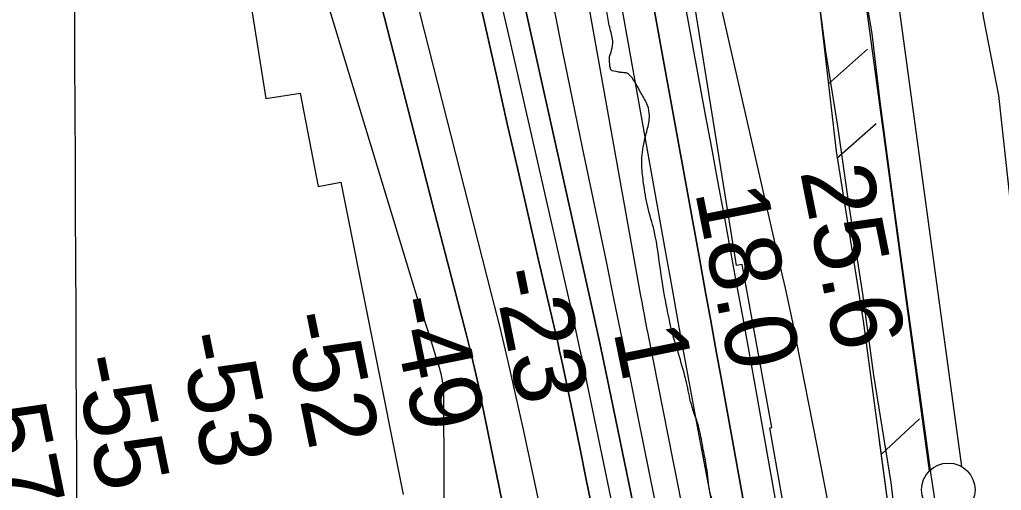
# Model space of a CAD drawing. Extents: x 3419139 to 3457078, y 540382 to 565875.
# Drawn here: x 3439010 to 3439927, y 553958 to 554398 of the extents above; entities that cross this region are included whole.
import ezdxf

# ---------------------------------------------------------------- set-up
doc = ezdxf.new("R2010")
doc.units = 0
for name, color, linetype in [('V-FLOD-BASE', 7, 'Continuous'), ('V-GRID-MAJR', 7, 'Continuous'), ('V-LEVE-TOET', 7, 'Continuous'), ('V-RIVR-EDGE', 7, 'Continuous'), ('V-RIVR-RANG', 7, 'Continuous'), ('V-RRAP-FSHR', 7, 'Continuous'), ('V-RRAP-RVMT', 7, 'Continuous'), ('V-SURV-LINE', 7, 'Continuous'), ('V-TOPO-DPTH', 7, 'Continuous'), ('V-TOPO-MAJR', 7, 'Continuous'), ('V-TOPO-MINR', 7, 'Continuous'), ('V-TOPO-WATR', 7, 'Continuous')]:
    doc.layers.add(name, color=color, linetype=linetype)

msp = doc.modelspace()

# ---------------------------------------------------------------- linework, layer by layer
at = {"layer": 'V-FLOD-BASE'}
msp.add_lwpolyline([(3439732.26, 554810.44), (3439729.04, 554757.67), (3439727.3, 554731.01), (3439727.56, 554720.62), (3439730.89, 554708.26), (3439738.97, 554680.73), (3439756.22, 554612.19), (3439779.58, 554519.49), (3439793.75, 554456.58), (3439805.94, 554385.24), (3439813.65, 554321.78), (3439825.79, 554230.52), (3439838.21, 554139.53), (3439850.64, 554050.23), (3439861.12, 553972.72), (3439871.35, 553905.32)], dxfattribs=at)
at = {"layer": 'V-GRID-MAJR'}
msp.add_spline([(3439098.77, 545841.13), (3439072.33, 551898.65), (3439045.89, 557959.64), (3439019.44, 564020.65), (3439019.42, 564024.1)], degree=3, dxfattribs=at)
at = {"layer": 'V-LEVE-TOET'}
for points in [[(3439831.14, 553904.45), (3439824, 553965.54), (3439807.98, 554065.87), (3439797.52, 554142.09), (3439784.54, 554226.44), (3439774.35, 554298.74), (3439763.02, 554368.52), (3439755.6, 554425.97), (3439747.08, 554499.67), (3439740.46, 554540.86), (3439732.42, 554577.58), (3439715.19, 554638.69), (3439705.74, 554670.93), (3439701.02, 554686.07), (3439697.68, 554697.28), (3439694.62, 554706.53), (3439693.79, 554711.01), (3439692.7, 554724.18), (3439694.18, 554758.08), (3439695.68, 554799.26), (3439691, 554838.2), (3439682.74, 554897.61), (3439664.2, 554994.02)], [(3439838.15, 554946.85), (3439848.36, 554881), (3439850.86, 554871.19), (3439853.91, 554856.89), (3439856.66, 554834.2), (3439855.48, 554808.7), (3439857.66, 554784.05), (3439867.27, 554698.3), (3439882.48, 554615.07), (3439891.04, 554559.86), (3439900.38, 554480.84), (3439910, 554400.98), (3439924.39, 554327.55), (3439935.64, 554224.99)]]:
    msp.add_lwpolyline(points, dxfattribs=at)
at = {"layer": 'V-RIVR-EDGE'}
msp.add_spline([(3439897.96, 552838.81), (3439895.18, 552852.91), (3439892.04, 552868.07), (3439889.26, 552883.93), (3439888.92, 552888.51), (3439886.81, 552890.99), (3439885.41, 552893.46), (3439884.71, 552896.28), (3439883.69, 552908.96), (3439881.25, 552919.89), (3439878.81, 552931.18), (3439877.42, 552939.99), (3439873.94, 552955.15), (3439875, 552957.61), (3439875.01, 552962.55), (3439873.97, 552969.24), (3439873.63, 552972.77), (3439870.47, 552980.18), (3439865.91, 552986.88), (3439863.81, 552992.53), (3439861.36, 552999.93), (3439860.32, 553005.57), (3439858.57, 553011.92), (3439857.18, 553017.91), (3439855.43, 553023.91), (3439852.28, 553031.32), (3439848.77, 553037.32), (3439845.62, 553045.08), (3439842.12, 553056.71), (3439838.28, 553071.17), (3439833.75, 553092.32), (3439828.87, 553114.18), (3439822.92, 553128.29), (3439821.87, 553133.93), (3439821.89, 553141.33), (3439820.5, 553150.5), (3439817.01, 553162.14), (3439815.97, 553169.89), (3439815.3, 553181.87), (3439812.88, 553202.32), (3439811.84, 553208.31), (3439810.44, 553213.6), (3439806.59, 553223.12), (3439803.44, 553233), (3439801.01, 553245.69), (3439798.2, 553251.33), (3439796.45, 553255.21), (3439794.35, 553261.56), (3439791.93, 553279.19), (3439786.69, 553298.23), (3439783.91, 553315.15), (3439782.87, 553320.08), (3439780.07, 553329.96), (3439779.04, 553338.42), (3439778, 553346.17), (3439774.51, 553358.87), (3439769.61, 553372.27), (3439764.01, 553387.79), (3439758.06, 553404.36), (3439752.81, 553419.53), (3439741.6, 553446.34), (3439736.69, 553454.1), (3439731.43, 553464.68), (3439730.38, 553469.97), (3439729.69, 553476.67), (3439729.72, 553486.54), (3439729.02, 553489), (3439726.91, 553492.18), (3439726.23, 553498.88), (3439724.85, 553513.68), (3439721.37, 553531.31), (3439717.55, 553552.81), (3439712.31, 553570.44), (3439710.22, 553579.61), (3439708.49, 553593.71), (3439705.02, 553614.16), (3439704.68, 553622.26), (3439704.69, 553626.49), (3439708.58, 553631.06), (3439711.06, 553635.28), (3439710.71, 553638.81), (3439709.32, 553643.75), (3439705.8, 553645.87), (3439697.71, 553653.64), (3439695.61, 553658.93), (3439695.27, 553664.92), (3439694.61, 553680.43), (3439696.73, 553685.01), (3439699.56, 553689.23), (3439699.22, 553692.75), (3439697.12, 553699.8), (3439696.09, 553710.03), (3439696.11, 553716.37), (3439695.45, 553735.75), (3439695.83, 553748.79), (3439695.16, 553762.53), (3439697.64, 553766.75), (3439697.65, 553771.33), (3439696.97, 553779.09), (3439694.87, 553788.26), (3439690.34, 553807.65), (3439684.39, 553823.52), (3439683.35, 553830.57), (3439684.77, 553836.2), (3439684.08, 553840.79), (3439681.63, 553846.78), (3439678.83, 553854.89), (3439676.03, 553862.3), (3439673.95, 553876.4), (3439675.37, 553880.98), (3439676.44, 553885.56), (3439676.45, 553890.84), (3439674, 553896.84), (3439671.54, 553900.02), (3439667.69, 553908.13), (3439664.21, 553925.76), (3439659.68, 553946.21), (3439656.87, 553950.09), (3439654.77, 553956.44), (3439651.65, 553979.7), (3439648.52, 553996.27), (3439644.69, 554015.66), (3439637.35, 554038.94), (3439632.82, 554059.03), (3439619.2, 554107.34), (3439614.67, 554128.14), (3439609.11, 554159.87), (3439602.52, 554201.12), (3439596.58, 554223.33), (3439592.76, 554245.19), (3439591.04, 554261.75), (3439592.85, 554281.83), (3439596.05, 554295.22), (3439598.2, 554308.6), (3439596.46, 554318.12), (3439590.5, 554329.41), (3439580.32, 554345.64), (3439576.45, 554348.47), (3439571.87, 554348.84), (3439568.35, 554349.55), (3439562.36, 554351.33), (3439561.32, 554354.85), (3439560.97, 554358.03), (3439560.98, 554363.31), (3439562.76, 554369.65), (3439563.84, 554378.46), (3439561.05, 554391.15), (3439558.27, 554405.96), (3439553.4, 554429.58), (3439551.66, 554441.91), (3439549.21, 554448.61), (3439546.76, 554453.55), (3439544.66, 554460.61), (3439543.98, 554469.77), (3439544, 554477.88), (3439543.91, 554480)], degree=3, dxfattribs=at)
at = {"layer": 'V-RRAP-FSHR'}
for p, q in [((3439765.38, 554338.41), (3439801.92, 554370.81)), ((3439773.39, 554268.87), (3439809.92, 554301.26)), ((3439814.68, 553991.95), (3439850.61, 554025.02))]:
    msp.add_line(p, q, dxfattribs=at)
for points in [[(3439522.98, 556207.72), (3439541.36, 556021.46), (3439583.01, 555683.8), (3439624.13, 555273.38), (3439659.87, 554983.57), (3439685.08, 554824.69), (3439679.82, 554747.46), (3439685.29, 554704.76), (3439700.93, 554669.09), (3439728.32, 554557.22), (3439747.43, 554494.51), (3439772.64, 554275.32), (3439797.96, 554116.78), (3439825.34, 553912.33), (3439849.7, 553822.93), (3439865.11, 553645.02), (3439856.59, 553600.9), (3439862.35, 553565.71), (3439888.28, 553542.26), (3439924.45, 553445.47), (3439970.85, 553198.92), (3440071.23, 552762.47), (3440155.84, 552373.79)], [(3439682.11, 554781.1), (3439679.82, 554747.46), (3439685.29, 554704.76), (3439700.93, 554669.09), (3439728.32, 554557.22), (3439747.43, 554494.51), (3439772.64, 554275.32), (3439773.57, 554269.54)], [(3439813, 554004.49), (3439825.34, 553912.33), (3439849.7, 553822.93), (3439865.11, 553645.02), (3439856.59, 553600.9), (3439862.35, 553565.71), (3439888.28, 553542.26), (3439900.63, 553509.2)]]:
    msp.add_lwpolyline(points, dxfattribs=at)
at = {"layer": 'V-RRAP-RVMT'}
for p, q in [((3439679.39, 554168.49), (3439631.56, 554467.84)), ((3439219.16, 554454.62), (3439239.75, 554324.66)), ((3439239.75, 554324.66), (3439271.69, 554329.71)), ((3439271.69, 554329.71), (3439288.6, 554242.37)), ((3439288.6, 554242.37), (3439309.87, 554246.37)), ((3439309.87, 554246.37), (3439367.96, 553954.28)), ((3439684.81, 554169.38), (3439679.39, 554168.49)), ((3439712.52, 554017.1), (3439684.81, 554169.38)), ((3439710.63, 554016.82), (3439712.52, 554017.1)), ((3439762.68, 553722.19), (3439710.63, 554016.82))]:
    msp.add_line(p, q, dxfattribs=at)
at = {"layer": 'V-SURV-LINE'}
for points in [[(3439859.95, 553976.63), (3439783.58, 554539.44)], [(3439813.31, 554543.47), (3439889.68, 553980.66)]]:
    msp.add_lwpolyline(points, dxfattribs=at)
msp.add_circle((3439877.5, 553958.84), 25, dxfattribs=at)
at = {"layer": 'V-TOPO-DPTH'}
for points in [[(3439203.43, 555059.91), (3439235.29, 554871.43), (3439239.31, 554849.29), (3439243.67, 554827.23), (3439248.56, 554805.27), (3439253.8, 554783.38), (3439317.33, 554531.21), (3439336.69, 554454.71), (3439356.15, 554378.23), (3439375.77, 554301.8), (3439395.5, 554225.4), (3439426.86, 554104.48), (3439430.86, 554088.52), (3439434.69, 554072.53), (3439438.27, 554056.47), (3439441.68, 554040.37), (3439463.36, 553933.74)], [(3439463.36, 553933.74), (3439441.68, 554040.37), (3439438.27, 554056.47), (3439434.69, 554072.53), (3439430.86, 554088.52), (3439426.86, 554104.48), (3439395.5, 554225.4), (3439375.77, 554301.8), (3439356.15, 554378.23), (3439336.69, 554454.71), (3439317.33, 554531.21), (3439253.8, 554783.38), (3439248.56, 554805.27), (3439243.67, 554827.23), (3439239.31, 554849.29), (3439235.29, 554871.43), (3439203.43, 555059.91)], [(3439545.27, 553938.31), (3439539.18, 553968.37), (3439533.02, 553998.41), (3439526.81, 554028.44), (3439517.11, 554075.09), (3439515.69, 554081.78), (3439514.25, 554088.47), (3439512.75, 554095.15), (3439511.23, 554101.83), (3439494.63, 554173.4), (3439484.82, 554215.86), (3439475.06, 554258.33), (3439465.37, 554300.82), (3439455.72, 554343.32), (3439351.98, 554802.09), (3439347.37, 554823.55), (3439343.06, 554845.07), (3439339.2, 554866.68), (3439335.65, 554888.34), (3439314.36, 555027.46)], [(3439314.36, 555027.46), (3439335.65, 554888.34), (3439339.2, 554866.68), (3439343.06, 554845.07), (3439347.37, 554823.55), (3439351.98, 554802.09), (3439455.72, 554343.32), (3439465.37, 554300.82), (3439475.06, 554258.33), (3439484.82, 554215.86), (3439494.63, 554173.4), (3439511.23, 554101.83), (3439512.75, 554095.15), (3439514.25, 554088.47), (3439515.69, 554081.78), (3439517.11, 554075.09), (3439526.81, 554028.44), (3439533.02, 553998.41), (3439539.18, 553968.37), (3439545.27, 553938.31)], [(3439632.19, 553926.82), (3439620.35, 553986.21), (3439597.32, 554103.01), (3439596.92, 554105.04), (3439596.72, 554106.06), (3439596.52, 554107.08), (3439594.64, 554116.78), (3439593.52, 554122.65), (3439592.41, 554128.52), (3439591.32, 554134.4), (3439590.26, 554140.29), (3439464.41, 554844.08), (3439462.37, 554855.83), (3439460.41, 554867.59), (3439458.57, 554879.37), (3439456.81, 554891.16), (3439446.89, 554960.06)], [(3439632.19, 553926.82), (3439620.35, 553986.21), (3439597.32, 554103.01), (3439596.92, 554105.04), (3439596.72, 554106.06), (3439596.52, 554107.08), (3439594.64, 554116.78), (3439593.52, 554122.65), (3439592.41, 554128.52), (3439591.32, 554134.4), (3439590.26, 554140.29), (3439464.41, 554844.08), (3439462.37, 554855.83), (3439460.41, 554867.59), (3439458.57, 554879.37), (3439456.81, 554891.16), (3439446.89, 554960.06)], [(3439578.87, 553554.05), (3439480.37, 554015.22), (3439473.38, 554047.05), (3439466.14, 554078.82), (3439458.53, 554110.5), (3439450.68, 554142.12), (3439321.07, 554651.19), (3439313.42, 554681.38), (3439305.81, 554711.58), (3439298.27, 554741.79), (3439290.77, 554772.02), (3439278.6, 554821.27), (3439277.28, 554826.89), (3439276.05, 554832.53), (3439274.95, 554838.19), (3439273.94, 554843.88), (3439267, 554885.72), (3439262.85, 554912.37), (3439259.05, 554939.07)], [(3439578.87, 553554.05), (3439480.37, 554015.22), (3439473.38, 554047.05), (3439466.14, 554078.82), (3439458.53, 554110.5), (3439450.68, 554142.12), (3439321.07, 554651.19), (3439313.42, 554681.38), (3439305.81, 554711.58), (3439298.27, 554741.79), (3439290.77, 554772.02), (3439278.6, 554821.27), (3439277.28, 554826.89), (3439276.05, 554832.53), (3439274.95, 554838.19), (3439273.94, 554843.88), (3439267, 554885.72), (3439262.85, 554912.37), (3439259.05, 554939.07)], [(3439372.86, 554936.32), (3439374.86, 554919.59), (3439376.88, 554902.87), (3439379.92, 554877.74), (3439380.45, 554873.58), (3439381, 554869.42), (3439381.6, 554865.27), (3439382.23, 554861.12), (3439383.23, 554854.74), (3439383.75, 554851.89), (3439383.94, 554850.95), (3439386.75, 554837.97), (3439388.36, 554830.54), (3439389.98, 554823.12), (3439391.62, 554815.69), (3439393.26, 554808.27), (3439540.61, 554146.82), (3439546.21, 554121.41), (3439551.72, 554095.98), (3439557.13, 554070.53), (3439562.45, 554045.07), (3439614.25, 553794.32)], [(3439372.86, 554936.32), (3439374.86, 554919.59), (3439376.88, 554902.87), (3439379.92, 554877.74), (3439380.45, 554873.58), (3439381, 554869.42), (3439381.6, 554865.27), (3439382.23, 554861.12), (3439383.23, 554854.74), (3439383.75, 554851.89), (3439383.94, 554850.95), (3439386.75, 554837.97), (3439388.36, 554830.54), (3439389.98, 554823.12), (3439391.62, 554815.69), (3439393.26, 554808.27), (3439540.61, 554146.82), (3439546.21, 554121.41), (3439551.72, 554095.98), (3439557.13, 554070.53), (3439562.45, 554045.07), (3439614.25, 553794.32)], [(3439511.82, 554940.94), (3439516.32, 554910.06), (3439520.99, 554879.2), (3439525.93, 554848.39), (3439531.06, 554817.6), (3439549.57, 554709.36), (3439564.22, 554624.49), (3439579.05, 554539.66), (3439594.14, 554454.88), (3439609.42, 554370.13), (3439645.17, 554173.51), (3439650.33, 554145.15), (3439655.48, 554116.78), (3439660.63, 554088.41), (3439665.77, 554060.04), (3439699.55, 553873.72)]]:
    msp.add_lwpolyline(points, dxfattribs=at)
at = {"layer": 'V-TOPO-MAJR'}
msp.add_lwpolyline([(3439178.91, 554803.18), (3439383.96, 554128.95), (3439387.1, 554119.52), (3439390.18, 554110.08), (3439393.19, 554100.6), (3439396.14, 554091.11), (3439401.07, 554074.98), (3439401.51, 554073.54), (3439402.33, 554070.65), (3439403.4, 554066.6), (3439403.61, 554065.66), (3439404.5, 554060.94), (3439404.86, 554058.24), (3439405.35, 554053.62), (3439405.54, 554051.18), (3439405.69, 554046.27), (3439406.4, 553892.49)], dxfattribs=at)
at = {"layer": 'V-TOPO-MINR'}
for points in [[(3439663.98, 553908.32), (3439654.24, 553958.91), (3439644.72, 554009.54), (3439639.16, 554039.67), (3439632.61, 554075.28), (3439626.11, 554110.89), (3439619.67, 554146.52), (3439613.27, 554182.15), (3439506.01, 554782.35), (3439503.36, 554797.51), (3439500.77, 554812.69), (3439498.29, 554827.87), (3439495.87, 554843.07), (3439493.57, 554858.29), (3439491.34, 554873.52), (3439489.21, 554888.76), (3439487.17, 554904.02), (3439417.47, 555437.48)], [(3439683.32, 553554.14), (3439587.45, 554028.26), (3439580.14, 554064.24), (3439572.79, 554100.21), (3439565.37, 554136.16), (3439557.91, 554172.11), (3439535.64, 554278.94), (3439517.35, 554368.37), (3439499.53, 554457.88), (3439482.39, 554547.53), (3439465.72, 554637.27), (3439435.74, 554802.15), (3439430.62, 554831.51), (3439425.79, 554860.92), (3439421.39, 554890.4), (3439417.27, 554919.92), (3439395.69, 555083.5)], [(3439203.43, 555059.91), (3439235.29, 554871.43), (3439239.31, 554849.29), (3439243.67, 554827.23), (3439248.56, 554805.27), (3439253.8, 554783.38), (3439317.33, 554531.21), (3439336.69, 554454.71), (3439356.15, 554378.23), (3439375.77, 554301.8), (3439395.5, 554225.4), (3439426.86, 554104.48), (3439430.86, 554088.52), (3439434.69, 554072.53), (3439438.27, 554056.47), (3439441.68, 554040.37), (3439463.36, 553933.74)], [(3439545.27, 553938.31), (3439539.18, 553968.37), (3439533.02, 553998.41), (3439526.81, 554028.44), (3439517.11, 554075.09), (3439515.69, 554081.78), (3439514.25, 554088.47), (3439512.75, 554095.15), (3439511.23, 554101.83), (3439494.63, 554173.4), (3439484.82, 554215.86), (3439475.06, 554258.33), (3439465.37, 554300.82), (3439455.72, 554343.32), (3439351.98, 554802.09), (3439347.37, 554823.55), (3439343.06, 554845.07), (3439339.2, 554866.68), (3439335.65, 554888.34), (3439314.36, 555027.46)], [(3439767.7, 553934), (3439754.96, 553999.87), (3439735.27, 554099.53), (3439732.05, 554115.5), (3439728.72, 554131.45), (3439725.26, 554147.37), (3439721.7, 554163.28), (3439670.53, 554387.3), (3439651.92, 554470.47), (3439633.8, 554553.75), (3439616.42, 554637.18), (3439599.52, 554720.71), (3439569.5, 554872.58), (3439568.04, 554880.27), (3439566.64, 554887.97), (3439565.35, 554895.69), (3439564.13, 554903.42), (3439556.79, 554952.07)], [(3439562.83, 553948.96), (3439539.79, 554060.08), (3439536.41, 554076.16), (3439532.97, 554092.22), (3439529.43, 554108.27), (3439525.83, 554124.3), (3439472.3, 554359.44), (3439453.82, 554440.96), (3439435.44, 554522.5), (3439417.2, 554604.07), (3439399.06, 554685.66), (3439367.87, 554826.5), (3439365.5, 554837.71), (3439363.27, 554848.95), (3439361.26, 554860.23), (3439359.38, 554871.53), (3439347.7, 554946.44)], [(3439578.87, 553554.05), (3439480.37, 554015.22), (3439473.38, 554047.05), (3439466.14, 554078.82), (3439458.53, 554110.5), (3439450.68, 554142.12), (3439321.07, 554651.19), (3439313.42, 554681.38), (3439305.81, 554711.58), (3439298.27, 554741.79), (3439290.77, 554772.02), (3439278.6, 554821.27), (3439277.28, 554826.89), (3439276.05, 554832.53), (3439274.95, 554838.19), (3439273.94, 554843.88), (3439267, 554885.72), (3439262.85, 554912.37), (3439259.05, 554939.07)], [(3439614.25, 553794.32), (3439562.45, 554045.07), (3439557.13, 554070.53), (3439551.72, 554095.98), (3439546.21, 554121.41), (3439540.61, 554146.82), (3439393.26, 554808.27), (3439391.62, 554815.69), (3439389.98, 554823.12), (3439388.36, 554830.54), (3439386.75, 554837.97), (3439383.94, 554850.95), (3439383.75, 554851.89), (3439383.23, 554854.74), (3439382.23, 554861.12), (3439381.6, 554865.27), (3439381, 554869.42), (3439380.45, 554873.58), (3439379.92, 554877.74), (3439376.88, 554902.87), (3439374.86, 554919.59), (3439372.86, 554936.32)], [(3439699.55, 553873.72), (3439665.77, 554060.04), (3439660.63, 554088.41), (3439655.48, 554116.78), (3439650.33, 554145.15), (3439645.17, 554173.51), (3439609.42, 554370.13), (3439594.14, 554454.88), (3439579.05, 554539.66), (3439564.22, 554624.49), (3439549.57, 554709.36), (3439531.06, 554817.6), (3439525.93, 554848.39), (3439520.99, 554879.2), (3439516.32, 554910.06), (3439511.82, 554940.94)], [(3439782.38, 553576.14), (3439696.25, 554060.41), (3439690.68, 554091.56), (3439685.06, 554122.71), (3439679.38, 554153.84), (3439673.65, 554184.97), (3439667.89, 554216.09), (3439662.14, 554247.21), (3439656.42, 554278.34), (3439650.7, 554309.47), (3439552.01, 554847.28), (3439548.74, 554865.59), (3439545.6, 554883.93), (3439542.65, 554902.3), (3439539.82, 554920.69)]]:
    msp.add_lwpolyline(points, dxfattribs=at)
at = {"layer": 'V-TOPO-WATR'}
msp.add_lwpolyline([(3439632.19, 553926.82), (3439620.35, 553986.21), (3439597.32, 554103.01), (3439596.92, 554105.04), (3439596.72, 554106.06), (3439596.52, 554107.08), (3439594.64, 554116.78), (3439593.52, 554122.65), (3439592.41, 554128.52), (3439591.32, 554134.4), (3439590.26, 554140.29), (3439464.41, 554844.08), (3439462.37, 554855.83), (3439460.41, 554867.59), (3439458.57, 554879.37), (3439456.81, 554891.16), (3439446.89, 554960.06)], dxfattribs=at)

# ---------------------------------------------------------------- texts
at = {"layer": 'V-RIVR-RANG'}
for s, rotation, p in [('25.6', 281.18833, (3439738.8, 554256.5)), ('18.0', 281.18833, (3439640.54, 554237.89)), ('-23', 281.47131, (3439451.23, 554162.12)), ('-49', 281.47131, (3439354.49, 554136.02)), ('-52', 281.47131, (3439255.44, 554121.28)), ('1', 281.47131, (3439564.33, 554107.58)), ('-53', 281.47131, (3439157.28, 554102.15)), ('-55', 281.47131, (3439059.55, 554080.96)), ('-57', 281.47131, (3438961.28, 554062.35))]:
    msp.add_text(s, height=67, rotation=rotation, dxfattribs=at).set_placement(p)

doc.saveas('drawing.dxf')
